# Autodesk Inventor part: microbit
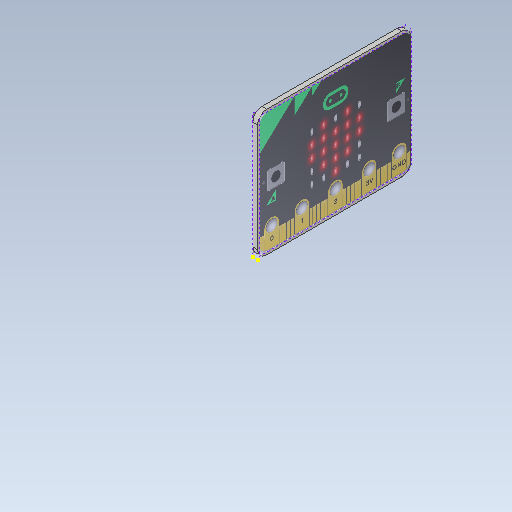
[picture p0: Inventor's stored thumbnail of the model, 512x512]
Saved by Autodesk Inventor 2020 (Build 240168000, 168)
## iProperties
Part Number: microbit
Material: Générique
Document SubType Name: Modeling
Designer: Buhl
Density: 1 g/cm^3
Appearance: Par défaut
Author: Buhl
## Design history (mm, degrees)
sketch "Esquisse1"
  geometry: L1 (3, 0)-(39, 0); L2 (42, -3)-(42, -48); L3 (39, -51)-(3, -51); L4 (0, -48)-(0, -3); A1 r 2 centre (40, -49) between (40, -51) and (42, -49); A2 r 2 centre (40, -2) between (42, -2) and (40, 0); A3 r 3 centre (39, -48) between (39, -51) and (42, -48); A4 r 3 centre (39, -3) between (42, -3) and (39, 0); A5 r 3 centre (3, -3) between (3, 0) and (0, -3); A6 r 3 centre (3, -48) between (0, -48) and (3, -51); 4 further points
  constraints: 12 point on circle, 12 point on line, 12 tangent, 8 end point, 6 centre point, 4 equal radius, 2 parallel, 1 horizontal, 1 perpendicular
  dimensions: "d0" = 42 distance of point (42, -51) point (0, -51); "d1" = 51 distance of point (42, 0) point (42, -51); "d2" = 2 radius of A1 (derived); "d3" = 3 radius of A3
extrude "Extrusion1" new body sketch "Esquisse1" distance "d4" = 1.6; taper "d5" = 0 deg
sketch "Esquisse2"
  geometry: L1 (0.566, 41.203)-(51.277, 41.203); L2 (51.277, 41.203)-(51.277, 0.803); L3 (51.277, 0.803)-(0.566, 0.803); L4 (0.566, 0.803)-(0.566, 41.203); 1 further point; 1 other entity
  constraints: 2 other
  node "Image1"
sketch "Esquisse3"
  geometry: L1 (-50.817, 41.619)-(-0.018, 41.619); L2 (-0.018, 41.619)-(-0.018, 0.936); L3 (-0.018, 0.936)-(-50.817, 0.936); L4 (-50.817, 0.936)-(-50.817, 41.619); 1 further point; 1 other entity
  constraints: 2 other
  node "Image2"
node "Solide1"
